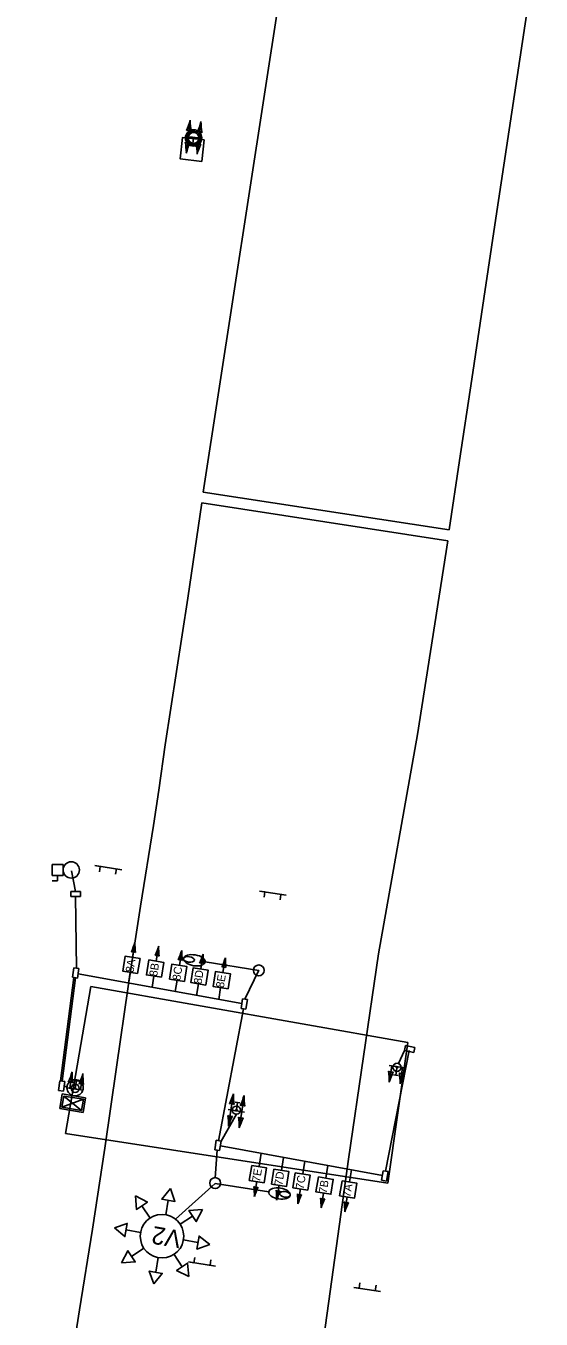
# Model space of a CAD drawing. Extents: x 991933 to 997296, y 1973751 to 1976728.
# Drawn here: x 992000.6 to 992095.4, y 1975513.6 to 1975751.3 of the extents above; entities that cross this region are included whole.
import ezdxf

# ---------------------------------------------------------------- set-up
doc = ezdxf.new("R2010")
doc.units = 0
for name, color, linetype in [('S_CROSS_DRAIN', 7, 'Continuous'), ('S_CURB', 7, 'Continuous'), ('S_DRIVEWAY', 7, 'Continuous'), ('S_DROP_INLET', 7, 'Continuous'), ('S_PARKING', 7, 'Continuous'), ('S_PAVEMENT_CROWN', 7, 'Continuous'), ('S_SIDEWALK', 7, 'Continuous'), ('S_WALL', 7, 'Continuous')]:
    doc.layers.add(name, color=color, linetype=linetype)

msp = doc.modelspace()

# ---------------------------------------------------------------- linework, layer by layer
at = {"layer": 'S_CROSS_DRAIN'}
for p, q in [((992013.26, 1975597.01), (992014.25, 1975596.85)), ((992013.26, 1975597.01), (992018.2, 1975596.24)), ((992014.25, 1975596.85), (992014.09, 1975595.86)), ((992017.06, 1975595.4), (992017.21, 1975596.39)), ((992043.54, 1975592.32), (992044.53, 1975592.17)), ((992043.54, 1975592.32), (992048.48, 1975591.55)), ((992044.53, 1975592.17), (992044.38, 1975591.18)), ((992047.34, 1975590.72), (992047.49, 1975591.71)), ((992030.49, 1975524.15), (992031.48, 1975523.99)), ((992030.49, 1975524.15), (992035.43, 1975523.38)), ((992031.48, 1975523.99), (992031.63, 1975524.98)), ((992034.6, 1975524.52), (992034.44, 1975523.54)), ((992060.88, 1975519.47), (992061.87, 1975519.32)), ((992060.88, 1975519.47), (992065.82, 1975518.71)), ((992061.87, 1975519.32), (992062.02, 1975520.3)), ((992064.99, 1975519.85), (992064.83, 1975518.86))]:
    msp.add_line(p, q, dxfattribs=at)
at = {"layer": 'S_CURB'}
for p, q in [((992030.44, 1975730.97), (992030.78, 1975733.97)), ((992032.42, 1975730.74), (992032.77, 1975733.74)), ((992032.92, 1975730.69), (992029.94, 1975731.03)), ((992030.44, 1975730.97), (992030.09, 1975727.97)), ((992031.28, 1975730.62), (992031.31, 1975730.87)), ((992031.28, 1975730.62), (992031.53, 1975730.6)), ((992031.55, 1975730.84), (992031.31, 1975730.87)), ((992031.55, 1975730.84), (992031.53, 1975730.6)), ((992032.42, 1975730.74), (992032.08, 1975727.74)), ((992070.35, 1975559.82), (992067.38, 1975560.26)), ((992067.88, 1975560.19), (992067.43, 1975557.2)), ((992068.71, 1975559.81), (992068.74, 1975560.06)), ((992068.71, 1975559.81), (992068.95, 1975559.77)), ((992068.99, 1975560.02), (992068.74, 1975560.06)), ((992068.99, 1975560.02), (992068.95, 1975559.77)), ((992069.86, 1975559.89), (992069.41, 1975556.91)), ((992008.63, 1975556.07), (992009.08, 1975559.05)), ((992010.61, 1975555.77), (992011.05, 1975558.76)), ((992008.13, 1975556.14), (992011.1, 1975555.7)), ((992009.49, 1975555.94), (992009.53, 1975556.18)), ((992009.49, 1975555.94), (992009.74, 1975555.9)), ((992009.78, 1975556.15), (992009.53, 1975556.18)), ((992009.78, 1975556.15), (992009.74, 1975555.9)), ((992038.3, 1975552.07), (992038.74, 1975555.06)), ((992040.27, 1975551.77), (992040.72, 1975554.76)), ((992037.8, 1975552.14), (992040.77, 1975551.7)), ((992038.3, 1975552.07), (992037.85, 1975549.08)), ((992039.16, 1975551.94), (992039.2, 1975552.19)), ((992039.45, 1975552.15), (992039.2, 1975552.19)), ((992039.45, 1975552.15), (992039.41, 1975551.9)), ((992039.16, 1975551.94), (992039.41, 1975551.9)), ((992040.27, 1975551.77), (992039.83, 1975548.79))]:
    msp.add_line(p, q, dxfattribs=at)
for centre, radius in [((992031.42, 1975730.74), 1.5), ((992031.42, 1975730.74), 1.25), ((992031.42, 1975730.74), 1), ((992043.42, 1975577.73), 1), ((992068.85, 1975559.92), 0.75), ((992009.63, 1975556.04), 0.75), ((992039.3, 1975552.05), 0.75), ((992035.39, 1975538.64), 1)]:
    msp.add_circle(centre, radius, dxfattribs=at)
for centre, radius, start, end in [((992016.56, 1975737.83), 14.74, 337.0766, 344.8147), ((992045.51, 1975734.5), 14.74, 182.0313, 189.7695), ((992018.55, 1975737.6), 14.74, 337.0766, 344.8147), ((992047.5, 1975734.27), 14.74, 182.0313, 189.7695), ((992030.48, 1975731.36), 0.814, 51.5757, 115.2703), ((992032.47, 1975731.13), 0.814, 51.5757, 115.2703), ((992030.39, 1975730.59), 0.814, 231.5757, 295.2703), ((992015.36, 1975727.45), 14.74, 2.0313, 9.7695), ((992044.31, 1975724.11), 14.74, 157.0766, 164.8147), ((992032.38, 1975730.36), 0.814, 231.5757, 295.2703), ((992017.35, 1975727.22), 14.74, 2.0313, 9.7695), ((992046.3, 1975723.88), 14.74, 157.0766, 164.8147), ((992067.82, 1975559.81), 0.814, 229.6217, 293.3163), ((992052.69, 1975557.18), 14.74, 0.0773, 7.8155), ((991994.99, 1975563.4), 14.74, 335.1226, 342.8607), ((992008.68, 1975556.45), 0.814, 49.6217, 113.3163), ((992023.81, 1975559.07), 14.74, 180.0773, 187.8155), ((991996.97, 1975563.1), 14.74, 335.1226, 342.8607), ((992010.66, 1975556.15), 0.814, 49.6217, 113.3163), ((992025.79, 1975558.78), 14.74, 180.0773, 187.8155), ((992081.51, 1975552.86), 14.74, 155.1226, 162.8607), ((992069.8, 1975559.51), 0.814, 229.6217, 293.3163), ((992054.67, 1975556.89), 14.74, 0.0773, 7.8155), ((992083.49, 1975552.56), 14.74, 155.1226, 162.8607), ((992024.66, 1975559.4), 14.74, 335.1226, 342.8607), ((992053.48, 1975555.08), 14.74, 180.0773, 187.8155), ((992026.64, 1975559.1), 14.74, 335.1226, 342.8607), ((992055.46, 1975554.78), 14.74, 180.0773, 187.8155), ((992038.35, 1975552.45), 0.814, 49.6217, 113.3163), ((992040.33, 1975552.16), 0.814, 49.6217, 113.3163), ((992038.24, 1975551.69), 0.814, 229.6217, 293.3164), ((992023.11, 1975549.06), 14.74, 0.0773, 7.8155), ((992051.93, 1975544.74), 14.74, 155.1226, 162.8607), ((992040.22, 1975551.39), 0.814, 229.6217, 293.3164), ((992025.09, 1975548.77), 14.74, 0.0773, 7.8155), ((992053.91, 1975544.44), 14.74, 155.1226, 162.8607)]:
    msp.add_arc(centre, radius, start, end, dxfattribs=at)
at = {"layer": 'S_DRIVEWAY'}
for p, q in [((992031.4, 1975730.61), (992031.25, 1975729.3)), ((992030.82, 1975729.35), (992031.68, 1975729.25)), ((992008.84, 1975592.25), (992008.84, 1975591.33)), ((992010.59, 1975592.25), (992008.84, 1975592.25)), ((992008.84, 1975591.33), (992010.59, 1975591.33)), ((992010.59, 1975591.33), (992010.59, 1975592.25)), ((992009.39, 1975578.19), (992009.16, 1975576.46)), ((992010.3, 1975578.07), (992009.39, 1975578.19)), ((992009.16, 1975576.46), (992010.07, 1975576.33)), ((992010.07, 1975576.33), (992010.3, 1975578.07)), ((992040.4, 1975572.49), (992040.15, 1975570.75)), ((992041.31, 1975572.36), (992040.4, 1975572.49)), ((992041.06, 1975570.62), (992041.31, 1975572.36)), ((992040.15, 1975570.75), (992041.06, 1975570.62)), ((992070.4, 1975563.92), (992070.21, 1975563.02)), ((992072.11, 1975563.57), (992070.4, 1975563.92)), ((992070.21, 1975563.02), (992071.93, 1975562.67)), ((992071.93, 1975562.67), (992072.11, 1975563.57)), ((992068.83, 1975559.79), (992068.63, 1975558.49)), ((992006.8, 1975557.41), (992006.57, 1975555.67)), ((992007.71, 1975557.28), (992006.8, 1975557.41)), ((992007.48, 1975555.55), (992007.71, 1975557.28)), ((992010.28, 1975557.4), (992009.42, 1975557.53)), ((992009.65, 1975556.17), (992009.85, 1975557.47)), ((992068.2, 1975558.56), (992069.07, 1975558.42)), ((992006.57, 1975555.67), (992007.48, 1975555.55)), ((992039.95, 1975553.41), (992039.09, 1975553.54)), ((992039.32, 1975552.17), (992039.52, 1975553.47)), ((992035.57, 1975546.5), (992035.3, 1975544.77)), ((992036.48, 1975546.36), (992035.57, 1975546.5)), ((992036.21, 1975544.63), (992036.48, 1975546.36)), ((992035.3, 1975544.77), (992036.21, 1975544.63)), ((992066.29, 1975540.89), (992066.02, 1975539.16)), ((992067.2, 1975540.75), (992066.29, 1975540.89)), ((992066.93, 1975539.02), (992067.2, 1975540.75)), ((992066.02, 1975539.16), (992066.93, 1975539.02))]:
    msp.add_line(p, q, dxfattribs=at)
at = {"layer": 'S_DROP_INLET'}
msp.add_lwpolyline([(992033.39, 1975730.38), (992032.93, 1975726.41), (992028.96, 1975726.87), (992029.41, 1975730.84)], close=True, dxfattribs=at)
at = {"layer": 'S_PARKING'}
for p, q in [((992005.41, 1975597.2), (992005.41, 1975595.2)), ((992005.41, 1975597.2), (992007.41, 1975597.2)), ((992007.41, 1975597.2), (992007.41, 1975595.2)), ((992005.41, 1975595.2), (992007.41, 1975595.2)), ((992006.41, 1975595.2), (992006.41, 1975594.2)), ((992009.72, 1975592.25), (992008.96, 1975596.06)), ((992005.41, 1975594.2), (992006.41, 1975594.2)), ((992009.72, 1975591.33), (992009.85, 1975578.13)), ((992009.39, 1975576.42), (992006.93, 1975557.42)), ((992009.72, 1975576.39), (992007.26, 1975557.35)), ((992010.17, 1975577.1), (992040.27, 1975571.62)), ((992043.43, 1975577.79), (992040.85, 1975572.42)), ((992040.6, 1975570.69), (992036.03, 1975546.43)), ((992066.75, 1975540.82), (992071.1, 1975563.03)), ((992070.21, 1975563.02), (992069.11, 1975560.62)), ((992007.6, 1975556.42), (992008.2, 1975556.42)), ((992039.33, 1975551.3), (992036.48, 1975546.36)), ((992036.35, 1975545.49), (992066.16, 1975540.03)), ((992035.76, 1975544.7), (992035.37, 1975539.58))]:
    msp.add_line(p, q, dxfattribs=at)
msp.add_circle((992008.91, 1975596.2), 1.5, dxfattribs=at)
at = {"layer": 'S_PAVEMENT_CROWN'}
for p, q in [((992007.25, 1975555.02), (992006.81, 1975552.32)), ((992007.52, 1975554.64), (992007.19, 1975552.59)), ((992011.52, 1975554.32), (992007.25, 1975555.02)), ((992011.15, 1975554.04), (992007.52, 1975554.64)), ((992010.79, 1975551.99), (992007.52, 1975554.64)), ((992011.08, 1975551.61), (992006.81, 1975552.32)), ((992007.19, 1975552.59), (992011.14, 1975554.04)), ((992010.81, 1975551.99), (992007.19, 1975552.59)), ((992011.15, 1975554.04), (992010.81, 1975551.99)), ((992011.52, 1975554.32), (992011.08, 1975551.61))]:
    msp.add_line(p, q, dxfattribs=at)
msp.add_circle((992009.63, 1975556.15), 1.5, dxfattribs=at)
at = {"layer": 'S_SIDEWALK'}
for p, q in [((992020.19, 1975580.12), (992020.63, 1975582.85)), ((992024.55, 1975579.43), (992024.99, 1975582.16)), ((992028.81, 1975578.66), (992029.25, 1975581.39)), ((992032.73, 1975578.01), (992033.17, 1975580.74)), ((992043.42, 1975577.73), (992033.54, 1975579.28)), ((992036.83, 1975577.32), (992037.27, 1975580.05)), ((992019.45, 1975575.41), (992019.76, 1975577.37)), ((992023.79, 1975574.62), (992024.12, 1975576.68)), ((992028.05, 1975573.84), (992028.38, 1975575.91)), ((992031.96, 1975573.13), (992032.3, 1975575.26)), ((992036.05, 1975572.39), (992036.4, 1975574.58)), ((992043.87, 1975544.11), (992043.47, 1975541.66)), ((992047.96, 1975543.36), (992047.57, 1975540.97)), ((992051.87, 1975542.65), (992051.49, 1975540.31)), ((992056.12, 1975541.87), (992055.74, 1975539.54)), ((992060.46, 1975541.07), (992060.1, 1975538.84)), ((992035.37, 1975538.58), (992028.12, 1975531.99)), ((992035.37, 1975538.58), (992045.25, 1975537.03)), ((992043.04, 1975538.92), (992042.59, 1975536.19)), ((992047.14, 1975538.23), (992046.69, 1975535.5)), ((992026.3, 1975532.81), (992026.77, 1975535.49)), ((992051.06, 1975537.57), (992050.61, 1975534.84)), ((992055.31, 1975536.8), (992054.87, 1975534.07)), ((992059.67, 1975536.1), (992059.23, 1975533.37)), ((992023.41, 1975532.21), (992021.92, 1975534.48)), ((992028.95, 1975531.07), (992031.22, 1975532.57)), ((992021.67, 1975529.56), (992019, 1975530.02)), ((992029.56, 1975528.18), (992032.23, 1975527.71)), ((992022.28, 1975526.67), (992020.01, 1975525.17)), ((992024.93, 1975524.93), (992024.46, 1975522.25)), ((992027.82, 1975525.53), (992029.31, 1975523.26))]:
    msp.add_line(p, q, dxfattribs=at)
for points in [[(992021.13, 1975577.15), (992018.39, 1975577.6), (992018.83, 1975580.34), (992021.57, 1975579.9)], [(992025.49, 1975576.46), (992022.75, 1975576.9), (992023.19, 1975579.65), (992025.93, 1975579.2)], [(992029.74, 1975575.69), (992027, 1975576.14), (992027.44, 1975578.88), (992030.18, 1975578.44)], [(992033.66, 1975575.04), (992030.92, 1975575.48), (992031.36, 1975578.23), (992034.1, 1975577.79)], [(992037.76, 1975574.36), (992035.02, 1975574.8), (992035.46, 1975577.54), (992038.2, 1975577.1)], [(992042.11, 1975541.88), (992044.85, 1975541.44), (992044.4, 1975538.7), (992041.66, 1975539.14)], [(992046.21, 1975541.19), (992048.95, 1975540.75), (992048.5, 1975538.01), (992045.76, 1975538.45)], [(992050.13, 1975540.54), (992052.87, 1975540.09), (992052.42, 1975537.35), (992049.68, 1975537.79)], [(992054.38, 1975539.76), (992057.12, 1975539.32), (992056.68, 1975536.58), (992053.93, 1975537.02)], [(992058.74, 1975539.06), (992061.48, 1975538.62), (992061.04, 1975535.88), (992058.29, 1975536.32)], [(992020.71, 1975536.3), (992020.9, 1975533.81), (992022.93, 1975535.15)], [(992027.15, 1975537.64), (992025.57, 1975535.7), (992027.97, 1975535.28)], [(992033.05, 1975533.77), (992030.55, 1975533.59), (992031.9, 1975531.55)], [(992016.84, 1975530.4), (992018.79, 1975528.82), (992019.21, 1975531.22)], [(992034.39, 1975527.34), (992032.44, 1975528.91), (992032.02, 1975526.51)], [(992018.18, 1975523.97), (992020.68, 1975524.15), (992019.33, 1975526.19)], [(992030.52, 1975521.44), (992030.33, 1975523.93), (992028.3, 1975522.59)], [(992024.08, 1975520.1), (992025.66, 1975522.04), (992023.26, 1975522.46)]]:
    msp.add_lwpolyline(points, close=True, dxfattribs=at)
msp.add_circle((992025.61, 1975528.87), 4, dxfattribs=at)
for centre, radius, start, end in [((992007.78, 1975586.96), 13.5, 334.5209, 342.2591), ((992020.25, 1975580.47), 0.746, 49.0201, 112.7147), ((992034.13, 1975582.73), 13.5, 179.4757, 187.2138), ((992012.14, 1975586.27), 13.5, 334.5209, 342.2591), ((992024.61, 1975579.78), 0.746, 49.0201, 112.7147), ((992038.49, 1975582.03), 13.5, 179.4757, 187.2138), ((992016.39, 1975585.5), 13.5, 334.5209, 342.2591), ((992042.75, 1975581.27), 13.5, 179.4757, 187.2138), ((992020.31, 1975584.85), 13.5, 334.5209, 342.2591), ((992046.67, 1975580.62), 13.5, 179.4757, 187.2138), ((992028.86, 1975579.01), 0.746, 49.0201, 112.7147), ((992032.78, 1975578.36), 0.746, 49.0201, 112.7147), ((992024.41, 1975584.17), 13.5, 334.5209, 342.2591), ((992036.89, 1975577.67), 0.746, 49.0201, 112.7147), ((992050.77, 1975579.93), 13.5, 179.4757, 187.2138), ((992042.98, 1975538.57), 0.746, 228.9434, 292.6381), ((992029.1, 1975536.33), 13.5, 359.3991, 7.1372), ((992055.45, 1975532.06), 13.5, 154.4443, 162.1824), ((992047.08, 1975537.88), 0.746, 228.9434, 292.6381), ((992033.2, 1975535.64), 13.5, 359.3991, 7.1372), ((992059.55, 1975531.37), 13.5, 154.4443, 162.1824), ((992051, 1975537.22), 0.746, 228.9434, 292.6381), ((992037.12, 1975534.98), 13.5, 359.3991, 7.1372), ((992063.47, 1975530.71), 13.5, 154.4443, 162.1824), ((992055.25, 1975536.45), 0.746, 228.9434, 292.6381), ((992041.37, 1975534.21), 13.5, 359.3991, 7.1372), ((992067.72, 1975529.94), 13.5, 154.4443, 162.1824), ((992059.61, 1975535.75), 0.746, 228.9434, 292.6381), ((992045.73, 1975533.51), 13.5, 359.3991, 7.1372), ((992072.08, 1975529.24), 13.5, 154.4443, 162.1824)]:
    msp.add_arc(centre, radius, start, end, dxfattribs=at)
for centre, major_axis in [((992031.57, 1975579.59), (-1.98, 0.31)), ((992030.58, 1975579.75), (0.988, -0.155)), ((992047.23, 1975536.72), (1.98, -0.31)), ((992048.22, 1975536.57), (-0.988, 0.155))]:
    msp.add_ellipse(centre, major_axis=major_axis, ratio=0.5, dxfattribs=at)
at = {"layer": 'S_WALL'}
for p, q in [((992033.19, 1975665.65), (992050.48, 1975778.04)), ((992078.47, 1975658.68), (992033.19, 1975665.65)), ((992032.91, 1975663.67), (992078.18, 1975656.7)), ((992078.18, 1975656.7), (992072.63, 1975621.12)), ((992007.83, 1975547.76), (992012.52, 1975574.76)), ((992012.52, 1975574.76), (992070.81, 1975564.48)), ((992070.81, 1975564.48), (992067.18, 1975538.6)), ((992067.18, 1975538.6), (992007.83, 1975547.76))]:
    msp.add_line(p, q, dxfattribs=at)
for points in [[(992095.36, 1975771.26), (992087.02, 1975715.99), (992084.81, 1975701.23), (992082.59, 1975686.4), (992080.35, 1975671.48), (992078.47, 1975658.68)], [(992000.56, 1975450.02), (992001.46, 1975456.11), (992003.72, 1975470.85), (992006.07, 1975485.68), (992008.13, 1975500.54), (992010.43, 1975515.34), (992012.81, 1975530.17), (992015.1, 1975545.07), (992017.26, 1975559.93), (992019.39, 1975574.75), (992021.66, 1975589.56), (992024.03, 1975604.36), (992025.04, 1975610.86), (992026.22, 1975619.18), (992026.22, 1975619.18), (992026.22, 1975619.18), (992026.22, 1975619.18), (992026.22, 1975619.18), (992030.39, 1975646.15), (992030.39, 1975646.15), (992030.39, 1975646.15), (992032.91, 1975663.67)], [(992072.63, 1975621.12), (992065.41, 1975580.76), (992059.93, 1975543.02), (992055.11, 1975508.56)]]:
    msp.add_lwpolyline(points, dxfattribs=at)

# ---------------------------------------------------------------- texts
at = {"layer": 'S_SIDEWALK'}
for s, height, rotation, p in [('8A', 1.489, 81.0947, (992020.35, 1975577.26)), ('8B', 1.489, 81.2506, (992024.71, 1975576.56)), ('8C', 1.489, 81.0947, (992028.96, 1975575.79)), ('8D', 1.489, 81.0947, (992032.88, 1975575.15)), ('8E', 1.489, 81.0947, (992036.98, 1975574.45)), ('7E', 1.489, 81.0947, (992043.63, 1975538.77)), ('7D', 1.489, 81.0947, (992047.73, 1975538.13)), ('7C', 1.489, 81.0947, (992051.65, 1975537.43)), ('7B', 1.489, 81.0947, (992055.9, 1975536.67)), ('7A', 1.489, 81.2506, (992060.26, 1975535.95)), ('V2', 3.25, 170.1027, (992029.31, 1975529.84))]:
    msp.add_text(s, height=height, rotation=rotation, dxfattribs=at).set_placement(p)

doc.saveas('drawing.dxf')
